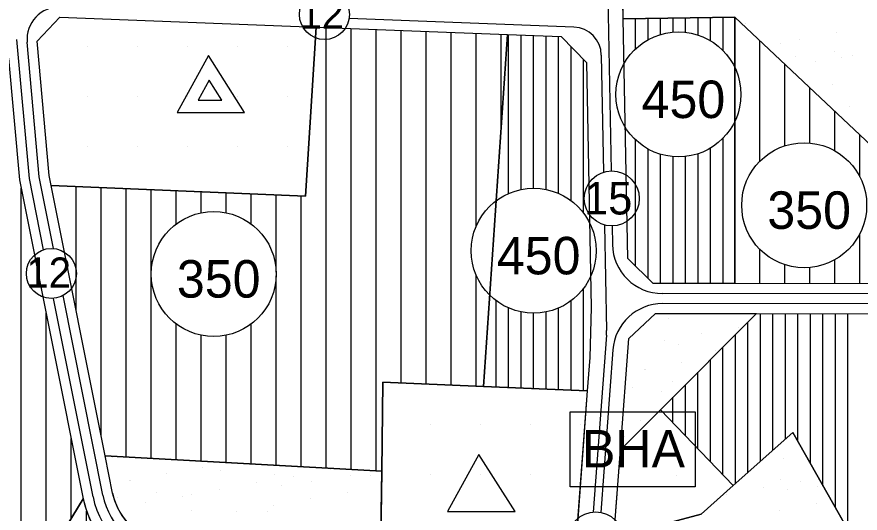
# Model space of a CAD drawing. Extents: x 419109 to 421295, y 4452223 to 4457798.
# Drawn here: x 420619.9 to 420957.3, y 4452419 to 4452617.5 of the extents above; entities that cross this region are included whole.
import ezdxf

# ---------------------------------------------------------------- set-up
doc = ezdxf.new("R2010")
doc.units = 0
for name, color, linetype in [('ADA', 7, 'Continuous'), ('ADAKENARI', 7, 'Continuous'), ('Default', 7, 'Continuous'), ('KALDIRIM', 7, 'Continuous'), ('KD_DAIRE', 7, 'Continuous'), ('KD_YGEN', 7, 'Continuous'), ('LJ_SEMBOL', 7, 'Continuous'), ('PL_AYA_PARK_DINLENME', 7, 'Continuous'), ('PL_K_BHA', 7, 'Continuous'), ('PL_KON_MEV_350', 7, 'Continuous'), ('PL_KON_MEV_450', 7, 'Continuous'), ('PL_SAY_ILKOGRETIM', 7, 'Continuous'), ('PL_SAY_ORTAOGRETIM', 7, 'Continuous'), ('SM_DAIRE', 7, 'Continuous'), ('SM_TAKS', 7, 'Continuous'), ('TR_ILKEGITIM', 7, 'Continuous'), ('TR_ORTAEGITIM', 7, 'Continuous'), ('TR_ORTAYOGUNKONUT', 7, 'Continuous'), ('TR_PARKALANI', 7, 'Continuous'), ('TR_YONETIMMERK', 7, 'Continuous'), ('TR_YUKSEKYOGUNKONUT', 7, 'Continuous')]:
    doc.layers.add(name, color=color, linetype=linetype)

# ---------------------------------------------------------------- blocks, each defined once
blk = doc.blocks.new('POINT_DISPLAY')
at = {"layer": 'Default'}
blk.add_line((0, 0), (0, 0), dxfattribs=at)

msp = doc.modelspace()

# ---------------------------------------------------------------- linework, layer by layer
at = {"layer": 'ADA'}
for p, q in [((420862.44, 4452616.65), (420907.13, 4452617.31)), ((420907.13, 4452617.31), (420961.75, 4452565.87)), ((420907.18, 4452510.79), (420907.13, 4452617.31)), ((420739.67, 4452613.4), (420735.36, 4452545.72)), ((420806.63, 4452469.62), (420816.21, 4452610.43)), ((420735.36, 4452545.72), (420633.65, 4452550.09)), ((420915.8, 4452498.79), (420877.39, 4452460.37)), ((420765.86, 4452435.83), (420766.28, 4452471.35)), ((420766.28, 4452471.35), (420806.63, 4452469.62)), ((420806.63, 4452469.62), (420848.1, 4452467.85)), ((420877.39, 4452460.37), (420861.39, 4452444.37)), ((420877.39, 4452460.37), (420906.49, 4452429.99)), ((420906.49, 4452429.99), (420930.36, 4452451.2)), ((420930.36, 4452451.2), (420955.76, 4452406.29)), ((420655.24, 4452441.92), (420765.86, 4452435.83)), ((420765.44, 4452400.08), (420765.86, 4452435.83)), ((420893.61, 4452418.54), (420906.49, 4452429.99)), ((420632.81, 4452402.34), (420646.45, 4452424.69))]:
    msp.add_line(p, q, dxfattribs=at)
at = {"layer": 'ADAKENARI'}
for p, q in [((420862.44, 4452616.65), (420862.05, 4452637.03)), ((420627.99, 4452607.82), (420637.08, 4452617.39)), ((420637.08, 4452617.39), (420739.67, 4452613.4)), ((420864.28, 4452520.82), (420862.44, 4452616.65)), ((420739.67, 4452613.4), (420816.21, 4452610.43)), ((420816.21, 4452610.43), (420837.59, 4452609.59)), ((420837.59, 4452609.59), (420847.78, 4452599.21)), ((420632.86, 4452554.03), (420627.99, 4452607.82)), ((420616.56, 4452601), (420620.97, 4452552.31)), ((420847.78, 4452599.21), (420849.65, 4452501.22)), ((420620.97, 4452552.31), (420646.45, 4452424.69)), ((420633.65, 4452550.09), (420632.86, 4452554.03)), ((420655.24, 4452441.92), (420633.65, 4452550.09)), ((420874.47, 4452510.82), (420864.28, 4452520.82)), ((420907.18, 4452510.79), (420874.47, 4452510.82)), ((420961.75, 4452510.75), (420907.18, 4452510.79)), ((420849.65, 4452501.22), (420849.1, 4452481.25)), ((420864.71, 4452488.85), (420875.46, 4452498.82)), ((420875.46, 4452498.82), (420915.8, 4452498.79)), ((420915.8, 4452498.79), (420961.13, 4452498.75)), ((420861.39, 4452444.37), (420864.71, 4452488.85)), ((420849.1, 4452481.25), (420848.1, 4452467.85)), ((420848.1, 4452467.85), (420843.31, 4452403.74)), ((420858.76, 4452409.21), (420861.39, 4452444.37)), ((420658.22, 4452427.04), (420655.24, 4452441.92))]:
    msp.add_line(p, q, dxfattribs=at)
for radius in [37, 25]:
    msp.add_arc((420682.73, 4452431.93), radius, 191.292, 265.3216, dxfattribs=at)
at = {"layer": 'KALDIRIM'}
for p, q in [((420856.05, 4452636.91), (420857.61, 4452555.84)), ((420842.76, 4452613.4), (420752.83, 4452616.89)), ((420624.93, 4452552.89), (420619.91, 4452608.39)), ((420628.89, 4452553.46), (420624.01, 4452607.39)), ((420853.72, 4452602.22), (420854.62, 4452555.35)), ((420630.62, 4452524.37), (420624.93, 4452552.89)), ((420634.61, 4452524.82), (420628.89, 4452553.46)), ((420855.02, 4452534.23), (420855.83, 4452491.99)), ((420858.03, 4452533.85), (420858.17, 4452526.43)), ((420650.37, 4452425.47), (420634.51, 4452504.89)), ((420654.29, 4452426.25), (420638.37, 4452506.02)), ((420974.4, 4452506.74), (420878.15, 4452506.82)), ((420973.56, 4452502.74), (420878.31, 4452502.82)), ((420855.78, 4452490.12), (420850.5, 4452419.43)), ((420858.35, 4452484.31), (420853.49, 4452419.29))]:
    msp.add_line(p, q, dxfattribs=at)
for centre, radius, start, end in [((420636.81, 4452608.55), 12.85, 87.7724, 185.1719), ((420842.31, 4452602), 11.41, 1.0983, 87.7724), ((420878.17, 4452526.82), 20, 181.0983, 269.9569), ((420878.3, 4452482.82), 20, 89.9569, 175.7244), ((420835.84, 4452491.61), 20, 355.7244, 1.0983), ((420682.73, 4452431.93), 33, 191.292, 265.3216), ((420682.73, 4452431.93), 29, 191.292, 265.3216)]:
    msp.add_arc(centre, radius, start, end, dxfattribs=at)
at = {"layer": 'KD_DAIRE'}
for centre, radius in [((420742.94, 4452618.39), 10), ((420857.89, 4452544.85), 11), ((420633.7, 4452514.86), 10), ((420851.47, 4452408.47), 11)]:
    msp.add_circle(centre, radius, dxfattribs=at)
at = {"layer": 'LJ_SEMBOL'}
for p, q in [((420696.54, 4452601.99), (420684, 4452579.17)), ((420711.02, 4452579.17), (420696.54, 4452601.99)), ((420696.85, 4452592.17), (420692.45, 4452584.17)), ((420701.92, 4452584.17), (420696.85, 4452592.17)), ((420692.45, 4452584.17), (420701.92, 4452584.17)), ((420684, 4452579.17), (420711.02, 4452579.17)), ((420804.72, 4452442.51), (420792.18, 4452419.7)), ((420819.2, 4452419.7), (420804.72, 4452442.51)), ((420841.26, 4452429.56), (420841.26, 4452429.56)), ((420792.18, 4452419.7), (420819.2, 4452419.7))]:
    msp.add_line(p, q, dxfattribs=at)
msp.add_lwpolyline([(420841.26, 4452459.56), (420891.26, 4452459.56), (420891.26, 4452429.56), (420841.26, 4452429.56), (420841.26, 4452459.56), (420891.26, 4452459.56)], dxfattribs=at)
at = {"layer": 'PL_AYA_PARK_DINLENME'}
msp.add_lwpolyline([(421111.62, 4452786.24), (421027.16, 4452585.56), (421011.92, 4452592.54), (420990.96, 4452542.37), (421045.97, 4452514.14), (421040.93, 4452510.69), (420961.75, 4452510.75), (420961.75, 4452565.87), (420907.13, 4452617.31), (420862.44, 4452616.65), (420862.05, 4452637.03)], dxfattribs=at)
for points in [[(420915.8, 4452498.79), (420877.39, 4452460.37), (420861.39, 4452444.37), (420864.71, 4452488.85), (420875.46, 4452498.82)], [(420955.76, 4452406.29), (420894.07, 4452409.01), (420857.93, 4452398.15), (420858.76, 4452409.21), (420893.61, 4452418.54), (420906.49, 4452429.99), (420930.36, 4452451.2)], [(420655.24, 4452441.92), (420765.86, 4452435.83), (420765.44, 4452400.08), (420680.69, 4452407.02), (420677.5, 4452407.49), (420674.39, 4452408.36), (420671.43, 4452409.64), (420668.65, 4452411.28), (420666.1, 4452413.27), (420663.84, 4452415.56), (420661.89, 4452418.13), (420660.28, 4452420.94), (420659.05, 4452423.92), (420658.22, 4452427.04)]]:
    msp.add_lwpolyline(points, close=True, dxfattribs=at)
at = {"layer": 'PL_K_BHA'}
msp.add_lwpolyline([(420858.76, 4452409.21), (420861.39, 4452444.37), (420877.39, 4452460.37), (420906.49, 4452429.99), (420893.61, 4452418.54)], close=True, dxfattribs=at)
at = {"layer": 'PL_KON_MEV_350'}
for points in [[(420961.75, 4452510.75), (420907.18, 4452510.79), (420907.13, 4452617.31), (420961.75, 4452565.87)], [(420816.21, 4452610.43), (420806.63, 4452469.62), (420766.28, 4452471.35), (420765.86, 4452435.83), (420655.24, 4452441.92), (420633.65, 4452550.09), (420735.36, 4452545.72), (420739.67, 4452613.4)]]:
    msp.add_lwpolyline(points, close=True, dxfattribs=at)
msp.add_lwpolyline([(420616.56, 4452601), (420620.97, 4452552.31), (420646.45, 4452424.69), (420632.81, 4452402.34), (420605.28, 4452389.43)], dxfattribs=at)
at = {"layer": 'PL_KON_MEV_450'}
for points in [[(420907.13, 4452617.31), (420907.18, 4452510.79), (420874.47, 4452510.82), (420864.28, 4452520.82), (420862.44, 4452616.65)], [(420806.63, 4452469.62), (420816.21, 4452610.43), (420837.59, 4452609.59), (420847.78, 4452599.21), (420849.65, 4452501.22), (420849.1, 4452481.25), (420848.1, 4452467.85)], [(420943.96, 4452333.26), (420890.44, 4452339.16), (420894.07, 4452409.01), (420955.76, 4452406.29), (420930.36, 4452451.2), (420906.49, 4452429.99), (420877.39, 4452460.37), (420915.8, 4452498.79), (420961.13, 4452498.75), (420961.65, 4452472.06), (421038.96, 4452492.38), (421042.67, 4452488.69), (421043.46, 4452373.99), (421023.35, 4452363.2), (421036.05, 4452320.56), (420975.68, 4452283.75), (420939.98, 4452286.94)], [(420773.35, 4452387.39), (420770.15, 4452348.3), (420747.65, 4452303.3), (420639.96, 4452312.09), (420632.81, 4452402.34), (420646.45, 4452424.69), (420647.44, 4452420.83), (420648.84, 4452417.1), (420650.63, 4452413.55), (420652.79, 4452410.2), (420655.3, 4452407.11), (420658.12, 4452404.3), (420661.23, 4452401.82), (420664.59, 4452399.68), (420668.17, 4452397.92), (420671.9, 4452396.55), (420675.77, 4452395.59), (420679.71, 4452395.06)]]:
    msp.add_lwpolyline(points, close=True, dxfattribs=at)
at = {"layer": 'PL_SAY_ILKOGRETIM'}
msp.add_lwpolyline([(420765.44, 4452400.08), (420765.86, 4452435.83), (420766.28, 4452471.35), (420806.63, 4452469.62), (420848.1, 4452467.85), (420843.31, 4452403.74), (420832.59, 4452394.59)], close=True, dxfattribs=at)
at = {"layer": 'PL_SAY_ORTAOGRETIM'}
msp.add_lwpolyline([(420735.36, 4452545.72), (420633.65, 4452550.09), (420632.86, 4452554.03), (420627.99, 4452607.82), (420637.08, 4452617.39), (420739.67, 4452613.4)], close=True, dxfattribs=at)
at = {"layer": 'SM_DAIRE'}
for centre in [(420884.57, 4452586.46), (420934.87, 4452542.14), (420826.66, 4452523.95), (420698.66, 4452514.63)]:
    msp.add_circle(centre, 25, dxfattribs=at)
at = {"layer": 'TR_ORTAYOGUNKONUT'}
for p, q in [((420743.65, 4452437.06), (420743.65, 4452613.25)), ((420753.65, 4452436.51), (420753.65, 4452612.86)), ((420763.65, 4452435.95), (420763.65, 4452612.47)), ((420773.65, 4452471.03), (420773.65, 4452612.08)), ((420783.65, 4452470.61), (420783.65, 4452611.69)), ((420793.65, 4452470.18), (420793.65, 4452611.3)), ((420803.65, 4452533.71), (420803.65, 4452610.91)), ((420813.65, 4452572.75), (420813.65, 4452610.53)), ((420917.13, 4452559.76), (420917.13, 4452607.89)), ((420927.13, 4452565.91), (420927.13, 4452598.47)), ((420937.13, 4452567.03), (420937.13, 4452589.05)), ((420947.13, 4452563.92), (420947.13, 4452579.64)), ((420957.13, 4452553.51), (420957.13, 4452570.22)), ((420621.62, 4452397.1), (420621.62, 4452549.02)), ((420643.65, 4452500.01), (420643.65, 4452549.66)), ((420653.65, 4452449.92), (420653.65, 4452549.23)), ((420663.65, 4452441.46), (420663.65, 4452548.8)), ((420673.65, 4452440.91), (420673.65, 4452548.37)), ((420683.65, 4452534.62), (420683.65, 4452547.94)), ((420693.65, 4452539.12), (420693.65, 4452547.51)), ((420703.65, 4452539.13), (420703.65, 4452547.08)), ((420713.65, 4452534.64), (420713.65, 4452546.65)), ((420723.65, 4452515.34), (420723.65, 4452546.22)), ((420733.65, 4452437.61), (420733.65, 4452545.8)), ((420957.13, 4452510.76), (420957.13, 4452530.77)), ((420917.13, 4452510.79), (420917.13, 4452524.52)), ((420947.13, 4452510.76), (420947.13, 4452520.35)), ((420927.13, 4452510.78), (420927.13, 4452518.36)), ((420937.13, 4452510.77), (420937.13, 4452517.24)), ((420723.65, 4452438.16), (420723.65, 4452513.93)), ((420803.65, 4452469.75), (420803.65, 4452514.19)), ((420631.62, 4452401.79), (420631.62, 4452498.93)), ((420683.65, 4452440.36), (420683.65, 4452494.64)), ((420713.65, 4452438.71), (420713.65, 4452494.62)), ((420693.65, 4452439.81), (420693.65, 4452490.14)), ((420703.65, 4452439.26), (420703.65, 4452490.13)), ((420641.62, 4452416.79), (420641.62, 4452448.85))]:
    msp.add_line(p, q, dxfattribs=at)
at = {"layer": 'TR_YUKSEKYOGUNKONUT'}
for p, q in [((420867.44, 4452604.67), (420867.44, 4452616.73)), ((420872.44, 4452608.32), (420872.44, 4452616.8)), ((420877.44, 4452610.42), (420877.44, 4452616.87)), ((420882.44, 4452611.37), (420882.44, 4452616.95)), ((420887.44, 4452611.29), (420887.44, 4452617.02)), ((420892.44, 4452610.19), (420892.44, 4452617.09)), ((420897.44, 4452607.89), (420897.44, 4452617.17)), ((420902.44, 4452603.94), (420902.44, 4452617.24)), ((420816.63, 4452546.85), (420816.63, 4452610.41)), ((420821.63, 4452548.44), (420821.63, 4452610.21)), ((420826.63, 4452548.95), (420826.63, 4452610.02)), ((420831.63, 4452548.45), (420831.63, 4452609.83)), ((420836.63, 4452546.87), (420836.63, 4452609.63)), ((420841.63, 4452543.97), (420841.63, 4452605.47)), ((420846.63, 4452538.99), (420846.63, 4452600.37)), ((420902.44, 4452510.8), (420902.44, 4452568.97)), ((420867.44, 4452517.72), (420867.44, 4452568.25)), ((420872.44, 4452512.81), (420872.44, 4452564.6)), ((420877.44, 4452510.82), (420877.44, 4452562.5)), ((420892.44, 4452510.8), (420892.44, 4452562.73)), ((420897.44, 4452510.8), (420897.44, 4452565.02)), ((420882.44, 4452510.81), (420882.44, 4452561.55)), ((420887.44, 4452510.81), (420887.44, 4452561.62)), ((420846.63, 4452467.91), (420846.63, 4452508.91)), ((420811.63, 4452469.41), (420811.63, 4452503.97)), ((420841.63, 4452468.12), (420841.63, 4452503.93)), ((420816.63, 4452469.19), (420816.63, 4452501.05)), ((420821.63, 4452468.98), (420821.63, 4452499.46)), ((420826.63, 4452468.77), (420826.63, 4452498.95)), ((420831.63, 4452468.55), (420831.63, 4452499.45)), ((420836.63, 4452468.34), (420836.63, 4452501.02)), ((420917.39, 4452439.67), (420917.39, 4452498.79)), ((420922.39, 4452444.11), (420922.39, 4452498.78)), ((420927.39, 4452448.56), (420927.39, 4452498.78)), ((420932.39, 4452447.61), (420932.39, 4452498.77)), ((420937.39, 4452438.77), (420937.39, 4452498.77)), ((420942.39, 4452429.93), (420942.39, 4452498.77)), ((420947.39, 4452421.09), (420947.39, 4452498.76)), ((420952.39, 4452412.25), (420952.39, 4452498.76)), ((420912.39, 4452435.23), (420912.39, 4452495.37)), ((420907.39, 4452430.78), (420907.39, 4452490.37)), ((420902.39, 4452434.28), (420902.39, 4452485.37)), ((420897.39, 4452439.49), (420897.39, 4452480.37)), ((420892.39, 4452444.71), (420892.39, 4452475.37)), ((420887.39, 4452449.93), (420887.39, 4452470.37)), ((420882.39, 4452455.15), (420882.39, 4452465.37)), ((420647.81, 4452311.45), (420647.81, 4452419.85))]:
    msp.add_line(p, q, dxfattribs=at)

# ---------------------------------------------------------------- block references
at = {"layer": 'TR_ILKEGITIM', "xscale": 0.1, "yscale": 0.10000000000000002}
for p in [(420785.44, 4452454.59), (420805.44, 4452454.59), (420825.44, 4452454.59), (420845.44, 4452454.59), (420785.44, 4452434.59), (420805.44, 4452434.59), (420825.44, 4452434.59), (420845.44, 4452434.59)]:
    msp.add_blockref('POINT_DISPLAY', p, dxfattribs=at)
at = {"layer": 'TR_ORTAEGITIM', "xscale": 0.1, "yscale": 0.10000000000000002}
for p in [(420647.99, 4452605.72), (420667.99, 4452605.72), (420687.99, 4452605.72), (420707.99, 4452605.72), (420727.99, 4452605.72), (420647.99, 4452585.72), (420667.99, 4452585.72), (420687.99, 4452585.72), (420707.99, 4452585.72), (420727.99, 4452585.72), (420647.99, 4452565.72), (420667.99, 4452565.72), (420687.99, 4452565.72), (420707.99, 4452565.72), (420727.99, 4452565.72)]:
    msp.add_blockref('POINT_DISPLAY', p, dxfattribs=at)
at = {"layer": 'TR_PARKALANI', "xscale": 0.1, "yscale": 0.10000000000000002}
for p in [(420911.46, 4452614.95), (420947.67, 4452611.18), (420925.26, 4452606.85), (420932.89, 4452608.58), (420946.85, 4452603.77), (420931.21, 4452601.45), (420939.55, 4452599.6), (420949.61, 4452601.17), (420954.33, 4452602.2), (420946.21, 4452590.62), (420952.87, 4452581.64), (420880.48, 4452496.76), (420870.73, 4452493.99), (420908.6, 4452493.32), (420879.06, 4452488.11), (420893.83, 4452490.71), (420884.63, 4452486.46), (420899.4, 4452483.86), (420885.72, 4452479.13), (420870.95, 4452476.52), (420871.59, 4452476.25), (420882.03, 4452471.69), (420866.39, 4452469.37), (420877.61, 4452467.54), (420869.5, 4452455.96), (420862.91, 4452449.68), (420658.15, 4452441.21), (420693.26, 4452439.57), (420694.35, 4452437.44), (420926.58, 4452440.72), (420679.58, 4452434.83), (420701.28, 4452435.92), (420722.81, 4452434.36), (420745.33, 4452436.27), (420753.22, 4452434.07), (420761.46, 4452434.2), (420664.81, 4452432.23), (420665.44, 4452431.96), (420715.78, 4452431.06), (420730.56, 4452433.67), (420737.58, 4452431.75), (420925.49, 4452432.42), (420933.24, 4452431.74), (420675.88, 4452427.4), (420701.01, 4452428.46), (420725.63, 4452430.24), (420751.99, 4452427.29), (420918.47, 4452429.13), (420928.31, 4452428.31), (420940.26, 4452429.82), (420660.24, 4452425.08), (420686.24, 4452425.85), (420689.79, 4452426.28), (420737.22, 4452424.69), (420903.7, 4452426.53), (420671.47, 4452423.25), (420722.44, 4452422.08), (420939.9, 4452422.76), (420689.79, 4452419.87), (420707.67, 4452419.48), (420720.2, 4452419.59), (420925.13, 4452420.15)]:
    msp.add_blockref('POINT_DISPLAY', p, dxfattribs=at)
at = {"layer": 'TR_YONETIMMERK', "xscale": 0.1, "yscale": 0.10000000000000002}
msp.add_blockref('POINT_DISPLAY', (420883.76, 4452434.21), dxfattribs=at)

# ---------------------------------------------------------------- texts
at = {"layer": 'KD_YGEN'}
for s, height, p in [('12', 12, (420732.97, 4452612.77)), ('15', 13, (420846.8, 4452538.45)), ('12', 12, (420623.72, 4452509.24))]:
    msp.add_text(s, height=height, dxfattribs=at).set_placement(p)
at = {"layer": 'LJ_SEMBOL'}
msp.add_text('BHA', height=15, dxfattribs=at).set_placement((420845.96, 4452437.26))
at = {"layer": 'SM_TAKS'}
for s, p in [('450', (420869.83, 4452577.01)), ('350', (420920.13, 4452532.69)), ('450', (420811.92, 4452514.5)), ('350', (420683.92, 4452505.19))]:
    msp.add_text(s, height=15, dxfattribs=at).set_placement(p)

doc.saveas('drawing.dxf')
